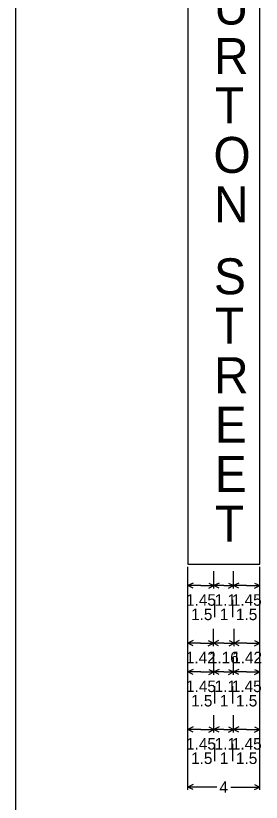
# Model space of a CAD drawing. Extents: x -16.4 to 26.5, y -12.9 to 9.1.
# Drawn here: x 0.61 to 3.21, y -7.94 to 0.39 of the extents above; entities that cross this region are included whole.
import ezdxf

# ---------------------------------------------------------------- set-up
doc = ezdxf.new("R2010")
doc.units = 0
doc.layers.add('SH_Text', color=7, linetype='Continuous')

msp = doc.modelspace()

# ---------------------------------------------------------------- linework, layer by layer
at = {"layer": 'SH_Text'}
for p, q in [((0.6059, -12.4069), (0.6059, 8.5931)), ((2.432, -7.8131), (2.432, -5.4509)), ((2.432, -5.6795), (2.432, -5.4966)), ((2.7088, -5.6795), (2.7088, -5.4966)), ((2.9172, -5.6795), (2.9172, -5.4966)), ((2.9172, -5.6795), (2.9172, -5.4966)), ((3.194, -7.8131), (3.194, -5.4509)), ((3.194, -5.6795), (3.194, -5.4966)), ((2.4865, -5.6218), (2.432, -5.649)), ((2.5705, -5.649), (2.432, -5.649)), ((2.4865, -5.6763), (2.432, -5.649)), ((2.5705, -5.649), (2.7088, -5.649)), ((2.6543, -5.6218), (2.7088, -5.649)), ((2.6543, -5.6763), (2.7088, -5.649)), ((2.7633, -5.6218), (2.7088, -5.649)), ((2.813, -5.649), (2.7088, -5.649)), ((2.7633, -5.6763), (2.7088, -5.649)), ((2.813, -5.649), (2.9172, -5.649)), ((2.8627, -5.6218), (2.9172, -5.649)), ((2.8627, -5.6763), (2.9172, -5.649)), ((2.9717, -5.6218), (2.9172, -5.649)), ((3.0555, -5.649), (2.9172, -5.649)), ((2.9717, -5.6763), (2.9172, -5.649)), ((3.0555, -5.649), (3.194, -5.649)), ((3.1395, -5.6218), (3.194, -5.649)), ((3.1395, -5.6763), (3.194, -5.649)), ((2.432, -5.9843), (2.432, -5.8014)), ((2.7178, -5.9843), (2.7178, -5.8014)), ((2.9083, -5.9843), (2.9083, -5.8014)), ((2.9083, -5.9843), (2.9083, -5.8014)), ((3.194, -5.9843), (3.194, -5.8014)), ((2.432, -6.2891), (2.432, -6.1062)), ((2.7029, -6.2891), (2.7029, -6.1062)), ((2.9231, -6.2891), (2.9231, -6.1062)), ((2.9231, -6.2891), (2.9231, -6.1062)), ((3.194, -6.2891), (3.194, -6.1062)), ((2.4865, -6.2314), (2.432, -6.2586)), ((2.6484, -6.2314), (2.7029, -6.2586)), ((2.7574, -6.2314), (2.7029, -6.2586)), ((2.8686, -6.2314), (2.9231, -6.2586)), ((2.9776, -6.2314), (2.9231, -6.2586)), ((3.1395, -6.2314), (3.194, -6.2586)), ((2.5675, -6.2586), (2.432, -6.2586)), ((2.4865, -6.2859), (2.432, -6.2586)), ((2.5675, -6.2586), (2.7029, -6.2586)), ((2.6484, -6.2859), (2.7029, -6.2586)), ((2.813, -6.2586), (2.7029, -6.2586)), ((2.7574, -6.2859), (2.7029, -6.2586)), ((2.813, -6.2586), (2.9231, -6.2586)), ((2.8686, -6.2859), (2.9231, -6.2586)), ((3.0586, -6.2586), (2.9231, -6.2586)), ((2.9776, -6.2859), (2.9231, -6.2586)), ((3.0586, -6.2586), (3.194, -6.2586)), ((3.1395, -6.2859), (3.194, -6.2586)), ((2.432, -6.5939), (2.432, -6.411)), ((2.7088, -6.5939), (2.7088, -6.411)), ((2.9172, -6.5939), (2.9172, -6.411)), ((2.9172, -6.5939), (2.9172, -6.411)), ((3.194, -6.5939), (3.194, -6.411)), ((2.4865, -6.5362), (2.432, -6.5634)), ((2.5705, -6.5634), (2.432, -6.5634)), ((2.4865, -6.5907), (2.432, -6.5634)), ((2.5705, -6.5634), (2.7088, -6.5634)), ((2.6543, -6.5362), (2.7088, -6.5634)), ((2.6543, -6.5907), (2.7088, -6.5634)), ((2.7633, -6.5362), (2.7088, -6.5634)), ((2.813, -6.5634), (2.7088, -6.5634)), ((2.7633, -6.5907), (2.7088, -6.5634)), ((2.813, -6.5634), (2.9172, -6.5634)), ((2.8627, -6.5362), (2.9172, -6.5634)), ((2.8627, -6.5907), (2.9172, -6.5634)), ((2.9717, -6.5362), (2.9172, -6.5634)), ((3.0555, -6.5634), (2.9172, -6.5634)), ((2.9717, -6.5907), (2.9172, -6.5634)), ((3.0555, -6.5634), (3.194, -6.5634)), ((3.1395, -6.5362), (3.194, -6.5634)), ((3.1395, -6.5907), (3.194, -6.5634)), ((2.432, -6.8987), (2.432, -6.7158)), ((2.7178, -6.8987), (2.7178, -6.7158)), ((2.9083, -6.8987), (2.9083, -6.7158)), ((2.9083, -6.8987), (2.9083, -6.7158)), ((3.194, -6.8987), (3.194, -6.7158)), ((2.432, -7.2035), (2.432, -7.0206)), ((2.7088, -7.2035), (2.7088, -7.0206)), ((2.9172, -7.2035), (2.9172, -7.0206)), ((2.9172, -7.2035), (2.9172, -7.0206)), ((3.194, -7.2035), (3.194, -7.0206)), ((2.4865, -7.1458), (2.432, -7.173)), ((2.6543, -7.1458), (2.7088, -7.173)), ((2.7633, -7.1458), (2.7088, -7.173)), ((2.8627, -7.1458), (2.9172, -7.173)), ((2.9717, -7.1458), (2.9172, -7.173)), ((3.1395, -7.1458), (3.194, -7.173)), ((2.5705, -7.173), (2.432, -7.173)), ((2.4865, -7.2003), (2.432, -7.173)), ((2.5705, -7.173), (2.7088, -7.173)), ((2.6543, -7.2003), (2.7088, -7.173)), ((2.813, -7.173), (2.7088, -7.173)), ((2.7633, -7.2003), (2.7088, -7.173)), ((2.813, -7.173), (2.9172, -7.173)), ((2.8627, -7.2003), (2.9172, -7.173)), ((3.0555, -7.173), (2.9172, -7.173)), ((2.9717, -7.2003), (2.9172, -7.173)), ((3.0555, -7.173), (3.194, -7.173)), ((3.1395, -7.2003), (3.194, -7.173)), ((2.432, -7.5083), (2.432, -7.3254)), ((2.7178, -7.5083), (2.7178, -7.3254)), ((2.9083, -7.5083), (2.9083, -7.3254)), ((2.9083, -7.5083), (2.9083, -7.3254)), ((3.194, -7.5083), (3.194, -7.3254)), ((2.4865, -7.7554), (2.432, -7.7826)), ((2.7387, -7.7826), (2.432, -7.7826)), ((2.4865, -7.8099), (2.432, -7.7826)), ((2.8873, -7.7826), (3.194, -7.7826)), ((3.1395, -7.7554), (3.194, -7.7826)), ((3.1395, -7.8099), (3.194, -7.7826))]:
    msp.add_line(p, q, dxfattribs=at)
msp.add_lwpolyline([(2.432, -5.4204), (3.194, -5.4204), (3.194, 1.4376), (2.432, 1.4376), (2.432, -5.4204), (2.432, -5.4204)], dxfattribs=at)

# ---------------------------------------------------------------- texts
for s, height, p in [('U', 0.381, (2.7088, 0.2946)), ('R', 0.381, (2.7088, -0.2293)), ('T', 0.381, (2.7178, -0.7532)), ('O', 0.381, (2.7029, -1.2771)), ('N', 0.381, (2.7088, -1.8009)), ('S', 0.381, (2.7088, -2.5629)), ('T', 0.381, (2.7178, -3.0868)), ('R', 0.381, (2.7088, -3.6107)), ('E', 0.381, (2.7178, -4.1346)), ('E', 0.381, (2.7178, -4.6584)), ('T', 0.381, (2.7178, -5.1823)), ('1.45', 0.12192, (2.4124, -5.8624)), ('1.1', 0.12192, (2.7161, -5.8624)), ('1.45', 0.12192, (2.8976, -5.8624)), ('1.5', 0.12192, (2.4657, -6.0148)), ('1', 0.1219, (2.7698, -6.0148)), ('1.5', 0.12192, (2.942, -6.0148)), ('1.42', 0.12192, (2.4105, -6.472)), ('1.16', 0.12192, (2.6543, -6.472)), ('1.42', 0.12192, (2.9016, -6.472)), ('1.45', 0.12192, (2.4124, -6.7768)), ('1.1', 0.12192, (2.7161, -6.7768)), ('1.45', 0.12192, (2.8976, -6.7768)), ('1.5', 0.12192, (2.4657, -6.9292)), ('1', 0.1219, (2.7698, -6.9292)), ('1.5', 0.12192, (2.942, -6.9292)), ('1.45', 0.12192, (2.4124, -7.3864)), ('1.1', 0.12192, (2.7161, -7.3864)), ('1.45', 0.12192, (2.8976, -7.3864)), ('1.5', 0.12192, (2.4657, -7.5388)), ('1', 0.1219, (2.7698, -7.5388)), ('1.5', 0.12192, (2.942, -7.5388)), ('4', 0.1219, (2.7669, -7.8436))]:
    msp.add_text(s, height=height, dxfattribs=at).set_placement(p)

doc.saveas('drawing.dxf')
